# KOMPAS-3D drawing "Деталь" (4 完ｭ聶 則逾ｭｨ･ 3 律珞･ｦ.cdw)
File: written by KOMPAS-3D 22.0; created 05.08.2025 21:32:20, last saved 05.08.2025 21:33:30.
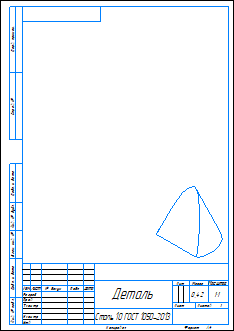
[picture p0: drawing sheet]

Sheet 1: A4, portrait

Document properties: Автор: user; Масса: 0.416415; Полное имя файла: G:\08 05 вторник\2025 НГ Лаб работы\Лаб 4 Сечение конуса\4 Чертежи\4 Конус Сечение 3 Чертеж.cdw

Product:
- Part/product: Деталь
    Масса: 0.348499

Title block, sheet 1: Наименование: Деталь; Материал: Сталь 10 ГОСТ 1050-2013; Масса: 0,42; Количество листов документа: 1; Форматы листов документа: A4; stored path: G:\08 05 вторник\2025 НГ Лаб работы\Лаб 4 Сечение конуса\4 Чертежи\4 Конус Сечение 5 Чертеж.cdw

Views: Изометрия 2
Dimensions and other numbers on the sheet: 1:1; 1; 0,42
